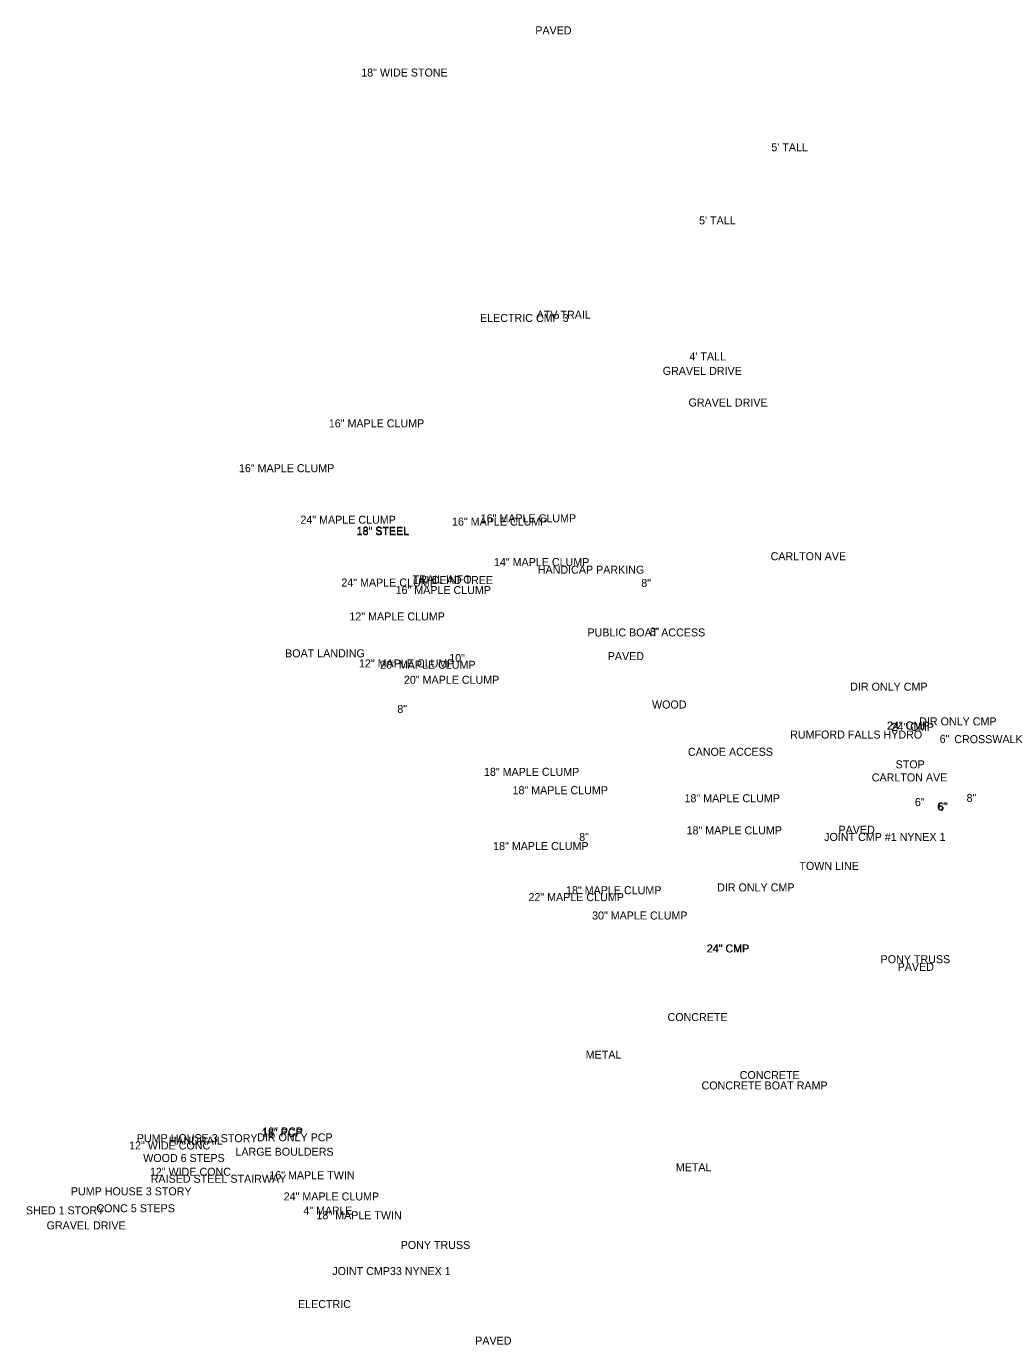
# Model space of a CAD drawing. Extents: x 939002 to 940105, y 627262 to 628202.
# Drawn here: x 939421 to 939724.4, y 627736.7 to 628148.6 of the extents above; entities that cross this region are included whole.
import ezdxf

# ---------------------------------------------------------------- set-up
doc = ezdxf.new("R2010")
doc.units = 0
for name, color, linetype in [('S_Annotation_Label', 7, 'Continuous'), ('S_Bridge_Curb', 7, 'Continuous'), ('S_Bridge_Rail', 7, 'Continuous'), ('S_Buildings_SillElevation', 7, 'Continuous'), ('S_Buildings_Steps_Brick', 7, 'Continuous'), ('S_Drainage_Culvert_Top', 7, 'Continuous'), ('S_Drainage_Invert', 7, 'Continuous'), ('S_Fencing_ChainLink', 7, 'Continuous'), ('S_Fencing_Picket', 7, 'Continuous'), ('S_Ground_Elevation', 7, 'Continuous'), ('S_Guardrail_Beam', 7, 'Continuous'), ('S_Misc_MiscFeature', 7, 'Continuous'), ('S_Misc_MiscItems', 7, 'Continuous'), ('S_Property_Walkways', 7, 'Continuous'), ('S_RetWall_Top', 7, 'Continuous'), ('S_Roadway_Centerline', 7, 'Continuous'), ('S_Roadway_Drive_Gravel', 7, 'Continuous'), ('S_Roadway_Edge_Pavement', 7, 'Continuous'), ('S_Roadway_Entr_Field_Wood', 7, 'Continuous'), ('S_Roadway_Sidewalks', 7, 'Continuous'), ('S_Traffic_Sign_DoublePost', 7, 'Continuous'), ('S_Traffic_Sign_SinglePost', 7, 'Continuous'), ('S_Trees_Dead_Pay', 7, 'Continuous'), ('S_Trees_Decid_NonPay', 7, 'Continuous'), ('S_Trees_Decid_Pay', 7, 'Continuous'), ('S_Utilities_Pole_Power', 7, 'Continuous'), ('S_Utilities_UG_Sanitary_Sewer', 7, 'Continuous'), ('S_Utilities_UG_Water_Line', 7, 'Continuous')]:
    doc.layers.add(name, color=color, linetype=linetype)

msp = doc.modelspace()

# ---------------------------------------------------------------- texts
at = {"layer": 'S_Annotation_Label'}
msp.add_text('CROSSWALK', height=2.5, dxfattribs=at).set_placement((939710.81, 627924.62))
at = {"layer": 'S_Bridge_Curb'}
for p in [(939621.25, 627837.8), (939643.79, 627819.68)]:
    msp.add_text('CONCRETE', height=2.5, dxfattribs=at).set_placement(p)
at = {"layer": 'S_Bridge_Rail'}
for p in [(939595.69, 627826.05), (939623.84, 627790.88)]:
    msp.add_text('METAL', height=2.5, dxfattribs=at).set_placement(p)
at = {"layer": 'S_Buildings_SillElevation'}
for s, p in [('PUMP HOUSE 3 STORY', (939455.49, 627799.96)), ('PUMP HOUSE 3 STORY', (939434.89, 627783.36)), ('SHED 1 STORY', (939420.85, 627777.4))]:
    msp.add_text(s, height=2.4999, dxfattribs=at).set_placement(p)
at = {"layer": 'S_Buildings_Steps_Brick'}
for s, p in [('WOOD 6 STEPS', (939457.49, 627793.77)), ('CONC 5 STEPS', (939442.86, 627778.06))]:
    msp.add_text(s, height=2.4999, dxfattribs=at).set_placement(p)
at = {"layer": 'S_Drainage_Culvert_Top'}
for s, height, p in [('18" STEEL', 2.5, (939524.16, 627989.54)), ('DIR ONLY CMP', 2.4999, (939678.31, 627941.02)), ('24" CMP', 2.5, (939689.87, 627928.87)), ('24" CMP', 2.5, (939691.22, 627928.44)), ('DIR ONLY CMP', 2.4999, (939699.86, 627930.18)), ('DIR ONLY CMP', 2.4999, (939636.75, 627878.31)), ('24" CMP', 2.5, (939633.58, 627859.23)), ('18" PCP', 2.5, (939494.53, 627801.63)), ('DIR ONLY PCP', 2.4999, (939493.07, 627800.22))]:
    msp.add_text(s, height=height, dxfattribs=at).set_placement(p)
at = {"layer": 'S_Drainage_Invert'}
for s, p in [('18" STEEL', (939524.12, 627989.81)), ('24" CMP', (939689.77, 627928.87)), ('24" CMP', (939691.22, 627928.47)), ('24" CMP', (939633.46, 627859.24)), ('18" PCP', (939494.68, 627802.06))]:
    msp.add_text(s, height=2.5, dxfattribs=at).set_placement(p)
at = {"layer": 'S_Fencing_ChainLink'}
for p in [(939653.68, 628109.53), (939631.1, 628086.7)]:
    msp.add_text("5' TALL", height=2.5, dxfattribs=at).set_placement(p)
at = {"layer": 'S_Fencing_Picket'}
msp.add_text("4' TALL", height=2.5, dxfattribs=at).set_placement((939628.09, 628044.2))
at = {"layer": 'S_Ground_Elevation'}
msp.add_text('BOAT LANDING', height=2.4999, dxfattribs=at).set_placement((939501.81, 627951.45))
at = {"layer": 'S_Guardrail_Beam'}
msp.add_text('WOOD', height=2.5, dxfattribs=at).set_placement((939616.41, 627935.45))
at = {"layer": 'S_Misc_MiscFeature'}
for s, height, p in [('PONY TRUSS', 2.5, (939687.8, 627855.87)), ('HANDRAIL', 2.5, (939465.44, 627799.22)), ('RAISED STEEL STAIRWAY', 2.4999, (939459.84, 627787.28)), ('PONY TRUSS', 2.5, (939537.9, 627766.6))]:
    msp.add_text(s, height=height, dxfattribs=at).set_placement(p)
at = {"layer": 'S_Misc_MiscItems'}
for s, p in [('CONCRETE BOAT RAMP', (939631.88, 627816.43)), ('LARGE BOULDERS', (939486.3, 627795.73))]:
    msp.add_text(s, height=2.4999, dxfattribs=at).set_placement(p)
at = {"layer": 'S_Property_Walkways'}
msp.add_text('PAVED', height=2.5, dxfattribs=at).set_placement((939602.58, 627950.56))
at = {"layer": 'S_RetWall_Top'}
for s, p in [('18" WIDE STONE', (939525.59, 628132.89)), ('12" WIDE CONC', (939453.09, 627797.68)), ('12" WIDE CONC', (939459.57, 627789.46))]:
    msp.add_text(s, height=2.4999, dxfattribs=at).set_placement(p)
at = {"layer": 'S_Roadway_Centerline'}
msp.add_text('CARLTON AVE', height=2.4999, dxfattribs=at).set_placement((939653.44, 627981.77))
at = {"layer": 'S_Roadway_Drive_Gravel'}
for p in [(939619.75, 628039.69), (939627.81, 628029.8), (939427.32, 627772.71)]:
    msp.add_text('GRAVEL DRIVE', height=2.4999, dxfattribs=at).set_placement(p)
at = {"layer": 'S_Roadway_Edge_Pavement'}
msp.add_text('PAVED', height=2.5, dxfattribs=at).set_placement((939579.95, 628146.06))
at = {"layer": 'S_Roadway_Entr_Field_Wood'}
msp.add_text('ATV TRAIL', height=2.5, dxfattribs=at).set_placement((939580.39, 628057.23))
at = {"layer": 'S_Roadway_Sidewalks'}
for p in [(939674.65, 627896.33), (939693.13, 627853.49), (939561.18, 627736.71)]:
    msp.add_text('PAVED', height=2.5, dxfattribs=at).set_placement(p)
at = {"layer": 'S_Traffic_Sign_DoublePost'}
msp.add_text('RUMFORD FALLS HYDRO', height=2.4999, dxfattribs=at).set_placement((939659.55, 627926.05))
at = {"layer": 'S_Traffic_Sign_SinglePost'}
for s, height, p in [('TRAIL INFO', 2.5, (939541.66, 627974.53)), ('HANDICAP PARKING', 2.4999, (939580.73, 627977.57)), ('PUBLIC BOAT ACCESS', 2.4999, (939596.24, 627957.96)), ('CANOE ACCESS', 2.4999, (939627.63, 627920.67)), ('STOP', 2.5, (939692.49, 627916.75)), ('CARLTON AVE', 2.4999, (939685.04, 627912.66)), ('TOWN LINE', 2.5, (939662.44, 627885.03))]:
    msp.add_text(s, height=height, dxfattribs=at).set_placement(p)
at = {"layer": 'S_Trees_Dead_Pay'}
msp.add_text('14" DEAD TREE', height=2.4999, dxfattribs=at).set_placement((939541.79, 627974.33))
at = {"layer": 'S_Trees_Decid_NonPay'}
for s, p in [('10"', (939553.07, 627949.96)), ('8"', (939536.85, 627934.05)), ('8"', (939593.66, 627894.06)), ('4" MAPLE', (939507.52, 627777.34))]:
    msp.add_text(s, height=2.5, dxfattribs=at).set_placement(p)
at = {"layer": 'S_Trees_Decid_Pay'}
for s, p in [('16" MAPLE CLUMP', (939515.46, 628023.28)), ('16" MAPLE CLUMP', (939487.39, 628009.28)), ('24" MAPLE CLUMP', (939506.59, 627993.18)), ('16" MAPLE CLUMP', (939553.94, 627992.59)), ('16" MAPLE CLUMP', (939562.9, 627993.63)), ('14" MAPLE CLUMP', (939567.04, 627979.94)), ('24" MAPLE CLUMP', (939519.38, 627973.56)), ('16" MAPLE CLUMP', (939536.32, 627971.21)), ('12" MAPLE CLUMP', (939521.9, 627962.97)), ('12" MAPLE CLUMP', (939524.89, 627948.29)), ('20" MAPLE CLUMP', (939531.49, 627947.87)), ('20" MAPLE CLUMP', (939538.92, 627943.18)), ('18" MAPLE CLUMP', (939563.92, 627914.41)), ('18" MAPLE CLUMP', (939572.84, 627908.67)), ('18" MAPLE CLUMP', (939626.56, 627906.17)), ('18" MAPLE CLUMP', (939627.2, 627896.14)), ('18" MAPLE CLUMP', (939566.78, 627891.23)), ('22" MAPLE CLUMP', (939577.81, 627875.27)), ('18" MAPLE CLUMP', (939589.55, 627877.43)), ('30" MAPLE CLUMP', (939597.68, 627869.53)), ('16" MAPLE TWIN', (939496.88, 627788.4)), ('24" MAPLE CLUMP', (939501.37, 627781.76)), ('18" MAPLE TWIN', (939511.6, 627775.87))]:
    msp.add_text(s, height=2.4999, dxfattribs=at).set_placement(p)
at = {"layer": 'S_Utilities_Pole_Power'}
for s, height, p in [('ELECTRIC CMP 3', 2.4999, (939562.69, 628056.22)), ('JOINT CMP #1 NYNEX 1', 2.4999, (939670.17, 627894.06)), ('JOINT CMP33 NYNEX 1', 2.4999, (939516.55, 627758.44)), ('ELECTRIC', 2.5, (939505.85, 627748.13))]:
    msp.add_text(s, height=height, dxfattribs=at).set_placement(p)
at = {"layer": 'S_Utilities_UG_Sanitary_Sewer'}
for p in [(939613.06, 627973.41), (939615.72, 627958.24)]:
    msp.add_text('8"', height=2.5, dxfattribs=at).set_placement(p)
at = {"layer": 'S_Utilities_UG_Water_Line'}
for s, p in [('6"', (939706.24, 627924.72)), ('6"', (939698.51, 627904.95)), ('6"', (939705.47, 627903.64)), ('6"', (939705.77, 627903.48)), ('8"', (939714.65, 627906.28))]:
    msp.add_text(s, height=2.5, dxfattribs=at).set_placement(p)

doc.saveas('drawing.dxf')
